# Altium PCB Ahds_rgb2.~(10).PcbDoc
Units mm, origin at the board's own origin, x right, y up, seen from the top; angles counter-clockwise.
Board outline 55.52 x 97.28 mm, 2 copper layers (Top Layer, Bottom Layer); 73 components, 40 nets, 226 pads, 37 vias.
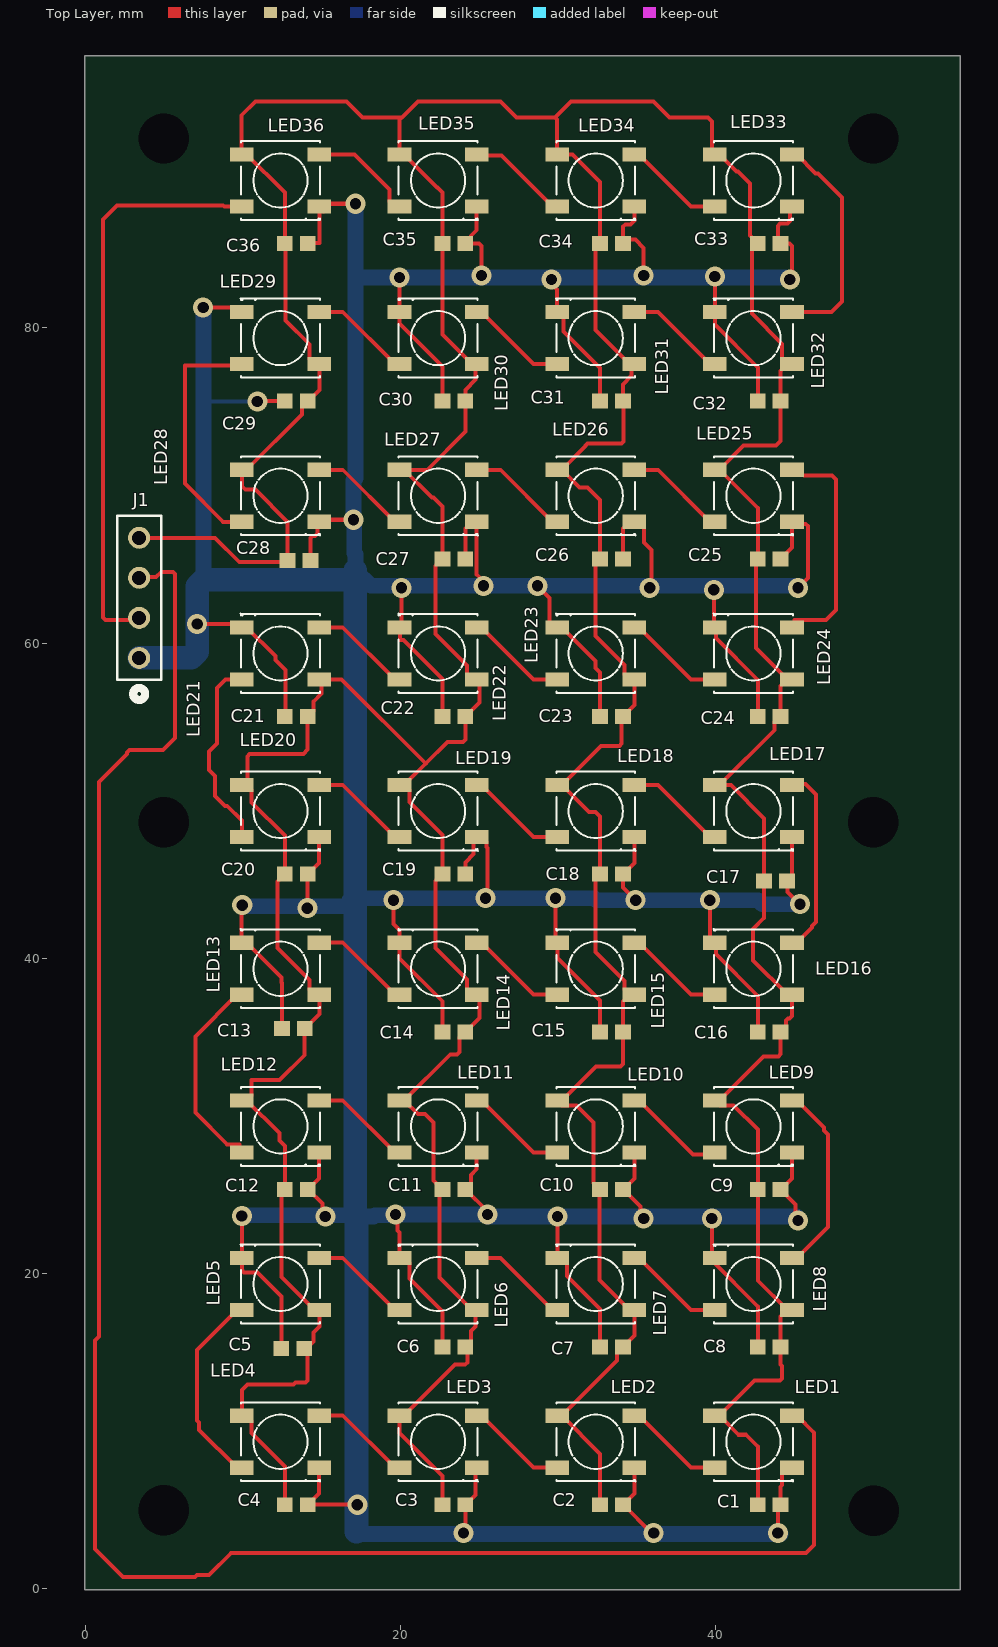
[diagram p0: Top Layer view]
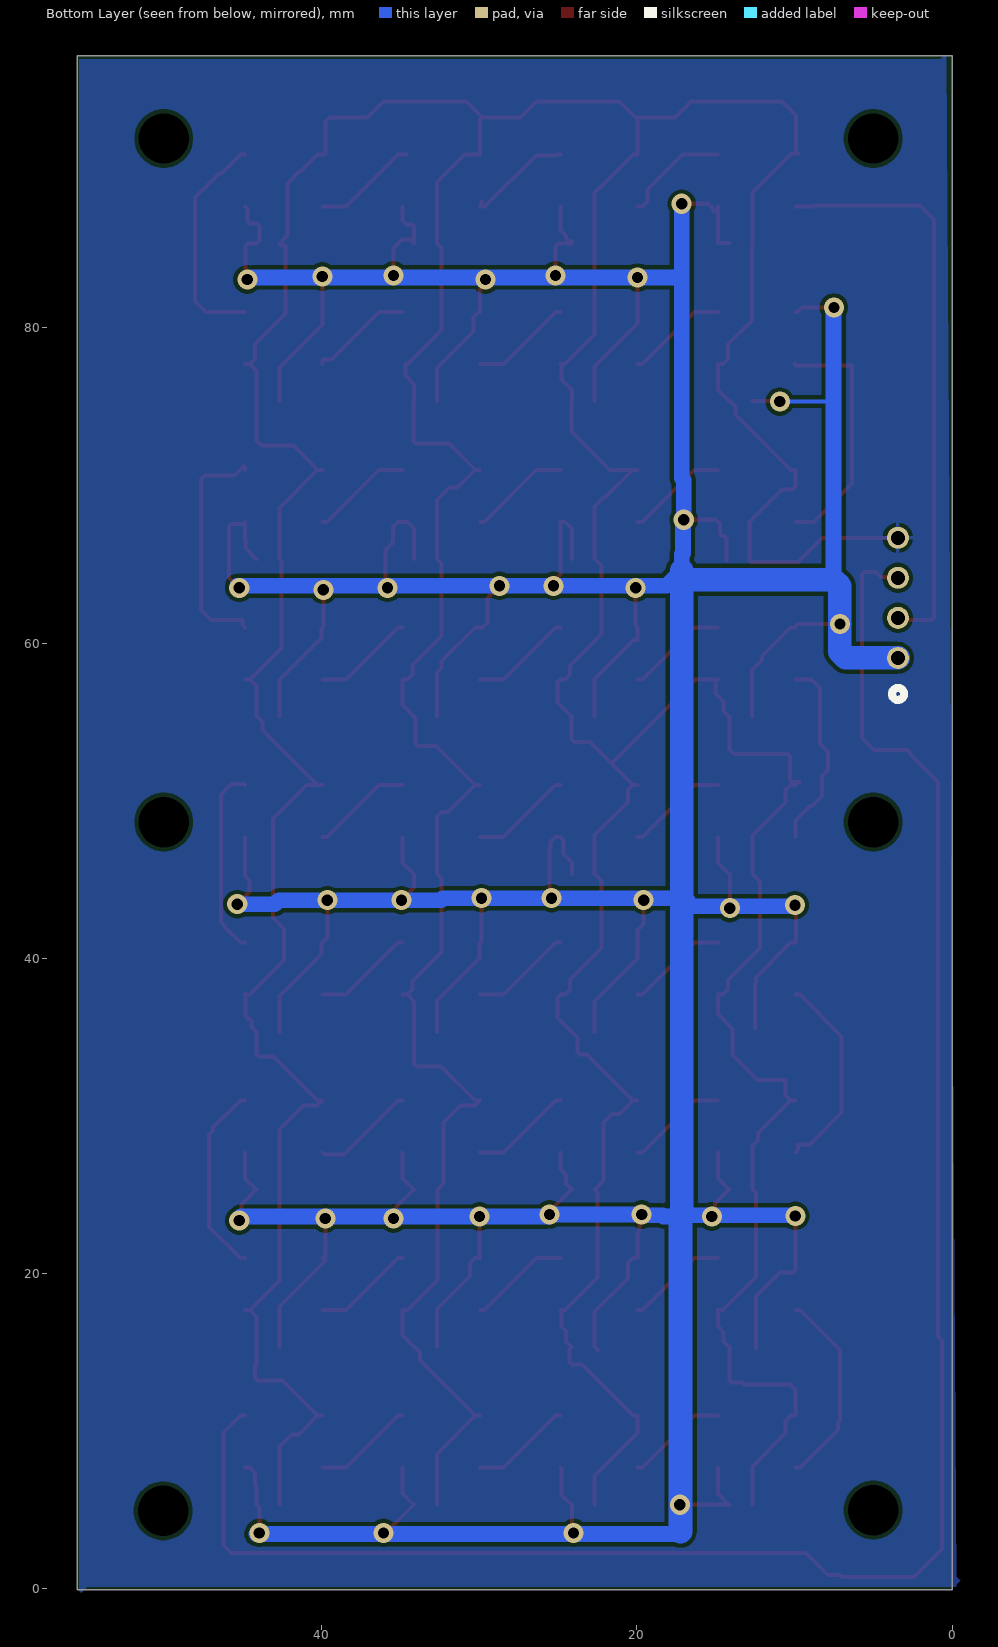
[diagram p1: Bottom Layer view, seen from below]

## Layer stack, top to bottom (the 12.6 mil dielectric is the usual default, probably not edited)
Top Solder: solder mask 0.0102, Solder Resist, Dk 3.5
Top Layer: signal copper 0.0356
Dielectric 1: dielectric 0.32, FR-4, Dk 4.8
Bottom Layer: signal copper 0.0356
Bottom Solder: solder mask 0.0102, Solder Resist, Dk 3.5

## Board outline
-0.018,-0.042 55.499,-0.042 55.499,97.24 -0.018,97.24

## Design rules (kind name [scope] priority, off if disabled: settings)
Clearance [All] p1: gap=0.254 ignorepadtopadclearanceinfootprint=TRUE
HoleSize [All] p1: absolutevalues=TRUE maxlimit=3.5 minlimit=0.025 maxpercent=80.000 minpercent=20.000
PolygonConnect [All] p1: connectstyle=Relief reliefconductorwidth=0.254 reliefentries=4 polygonreliefangle="90 Angle" airgapwidth=0.254
RoutingVias [All] p1: holewidth=0.711 width=1.27 viastyle="Through Hole" minholewidth=0.711 minwidth=1.27 maxholewidth=0.711 maxwidth=1.27
SolderMaskExpansion [All] p1: expansion=0.102 istentingtop=FALSE
Width [All] p1: maxlimit=2 minlimit=0.254 preferedwidth=0.254 minimp=50.000000 maximp=50.000000 favimp=50.000000
29 further rules are at their usual default settings.

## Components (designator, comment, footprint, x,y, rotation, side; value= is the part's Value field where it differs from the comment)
C1 "100nF" CAPC17595_87N_KEM#1 43.393,5.339 r180 top
C2 "100nF" CAPC17595_87N_KEM#1 33.393,5.339 r180 top
C3 "100nF" CAPC17595_87N_KEM#2 23.393,5.339 r180 top
C4 "100nF" CAPC17595_87N_KEM#3 13.393,5.339 r180 top
C5 "100nF" CAPC17595_87N_KEM#1 13.171,15.24 r0 top
C6 "100nF" CAPC17595_87N_KEM#1 23.393,15.339 r0 top
C7 "100nF" CAPC17595_87N_KEM#1 33.393,15.339 r0 top
C8 "100nF" CAPC17595_87N_KEM#1 43.393,15.339 r0 top
C9 "100nF" CAPC17595_87N_KEM#1 43.393,25.339 r180 top
C10 "100nF" CAPC17595_87N_KEM#1 33.393,25.339 r180 top
C11 "100nF" CAPC17595_87N_KEM#1 23.393,25.339 r180 top
C12 "100nF" CAPC17595_87N_KEM#1 13.393,25.339 r180 top
C13 "100nF" CAPC17595_87N_KEM#1 13.208,35.56 r0 top
C14 "100nF" CAPC17595_87N_KEM#1 23.393,35.339 r0 top
C15 "100nF" CAPC17595_87N_KEM#1 33.393,35.339 r0 top
C16 "100nF" CAPC17595_87N_KEM#1 43.393,35.339 r0 top
C17 "100nF" CAPC17595_87N_KEM#1 43.797,44.916 r180 top
C18 "100nF" CAPC17595_87N_KEM#1 33.393,45.339 r180 top
C19 "100nF" CAPC17595_87N_KEM#1 23.393,45.339 r180 top
C20 "100nF" CAPC17595_87N_KEM#1 13.393,45.339 r180 top
C21 "100nF" CAPC17595_87N_KEM#1 13.393,55.339 r0 top
C22 "100nF" CAPC17595_87N_KEM#1 23.393,55.339 r0 top
C23 "100nF" CAPC17595_87N_KEM#1 33.393,55.339 r0 top
C24 "100nF" CAPC17595_87N_KEM#1 43.393,55.339 r0 top
C25 "100nF" CAPC17595_87N_KEM#1 43.393,65.339 r180 top
C26 "100nF" CAPC17595_87N_KEM#1 33.393,65.339 r180 top
C27 "100nF" CAPC17595_87N_KEM#1 23.393,65.339 r180 top
C28 "100nF" CAPC17595_87N_KEM#1 13.571,65.236 r180 top
C29 "100nF" CAPC17595_87N_KEM#1 13.393,75.339 r0 top
C30 "100nF" CAPC17595_87N_KEM#1 23.393,75.339 r0 top
C31 "100nF" CAPC17595_87N_KEM#1 33.393,75.339 r0 top
C32 "100nF" CAPC17595_87N_KEM#1 43.393,75.339 r0 top
C33 "100nF" CAPC17595_87N_KEM#1 43.393,85.339 r180 top
C34 "100nF" CAPC17595_87N_KEM#1 33.393,85.339 r180 top
C35 "100nF" CAPC17595_87N_KEM#1 23.393,85.339 r180 top
C36 "100nF" CAPC17595_87N_KEM#1 13.393,85.339 r180 top
J1 "901471304" CONN04_901471304_MOL 3.429,59.055 r90 top
LED1 "WS2812B" *WS2812B_WS2812B(Primary) 42.393,9.339 r0 top
LED2 "WS2812B" *WS2812B_WS2812B(Primary) 32.393,9.339 r0 top
LED3 "WS2812B" *WS2812B_WS2812B(Primary) 22.393,9.339 r0 top
LED4 "WS2812B" *WS2812B_WS2812B(Primary) 12.393,9.339 r0 top
LED5 "WS2812B" *WS2812B_WS2812B(Primary) 12.393,19.339 r180 top
LED6 "WS2812B" *WS2812B_WS2812B(Primary) 22.393,19.339 r180 top
LED7 "WS2812B" *WS2812B_WS2812B(Primary) 32.393,19.339 r180 top
LED8 "WS2812B" *WS2812B_WS2812B(Primary) 42.393,19.339 r180 top
LED9 "WS2812B" *WS2812B_WS2812B(Primary) 42.393,29.339 r0 top
LED10 "WS2812B" *WS2812B_WS2812B(Primary) 32.393,29.339 r0 top
LED11 "WS2812B" *WS2812B_WS2812B(Primary) 22.393,29.339 r0 top
LED12 "WS2812B" *WS2812B_WS2812B(Primary) 12.393,29.339 r0 top
LED13 "WS2812B" *WS2812B_WS2812B(Primary) 12.393,39.339 r180 top
LED14 "WS2812B" *WS2812B_WS2812B(Primary) 22.393,39.339 r180 top
LED15 "WS2812B" *WS2812B_WS2812B(Primary) 32.393,39.339 r180 top
LED16 "WS2812B" *WS2812B_WS2812B(Primary) 42.393,39.339 r180 top
LED17 "WS2812B" *WS2812B_WS2812B(Primary) 42.393,49.339 r0 top
LED18 "WS2812B" *WS2812B_WS2812B(Primary) 32.393,49.339 r0 top
LED19 "WS2812B" *WS2812B_WS2812B(Primary) 22.393,49.339 r0 top
LED20 "WS2812B" *WS2812B_WS2812B(Primary) 12.393,49.339 r0 top
LED21 "WS2812B" *WS2812B_WS2812B(Primary) 12.393,59.339 r180 top
LED22 "WS2812B" *WS2812B_WS2812B(Primary) 22.393,59.339 r180 top
LED23 "WS2812B" *WS2812B_WS2812B(Primary) 32.393,59.339 r180 top
LED24 "WS2812B" *WS2812B_WS2812B(Primary) 42.393,59.339 r180 top
LED25 "WS2812B" *WS2812B_WS2812B(Primary) 42.393,69.339 r0 top
LED26 "WS2812B" *WS2812B_WS2812B(Primary) 32.393,69.339 r0 top
LED27 "WS2812B" *WS2812B_WS2812B(Primary) 22.393,69.339 r0 top
LED28 "WS2812B" *WS2812B_WS2812B(Primary) 12.393,69.339 r0 top
LED29 "WS2812B" *WS2812B_WS2812B(Primary) 12.393,79.339 r180 top
LED30 "WS2812B" *WS2812B_WS2812B(Primary) 22.393,79.339 r180 top
LED31 "WS2812B" *WS2812B_WS2812B(Primary) 32.393,79.339 r180 top
LED32 "WS2812B" *WS2812B_WS2812B(Primary) 42.393,79.339 r180 top
LED33 "WS2812B" *WS2812B_WS2812B(Primary) 42.393,89.339 r0 top
LED34 "WS2812B" *WS2812B_WS2812B(Primary) 32.393,89.339 r0 top
LED35 "WS2812B" *WS2812B_WS2812B(Primary) 22.393,89.339 r0 top
LED36 "WS2812B" *WS2812B_WS2812B(Primary) 12.393,89.339 r0 top

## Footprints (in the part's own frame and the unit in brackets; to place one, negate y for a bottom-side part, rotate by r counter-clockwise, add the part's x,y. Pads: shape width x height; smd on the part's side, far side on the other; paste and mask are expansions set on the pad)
*WS2812B_WS2812B(Primary) [mm]
  rect 1.5x0.9 smd: 1(2.45,-1.65) 2(2.45,1.65) 3(-2.45,1.65) 4(-2.45,-1.65)
  silkscreen extent -2.5,-2.52 2.52,2.5
CAPC17595_87N_KEM#1 [mm]
  rect 1x0.95 smd paste+0 mask+0: 1(-0.725,0) 2(0.725,0)
  body extent -0.87,-0.48 0.87,0.48, height 0.87
CAPC17595_87N_KEM#2 [mm]
  rect 1x0.95 smd paste+0.1 mask+0.1: 1(-0.725,0) 2(0.725,0)
  body extent -0.87,-0.48 0.87,0.48, height 0.87
CAPC17595_87N_KEM#3 [mm]
  rect 1x0.95 smd paste+0.102 mask+0: 1(-0.725,0)
  rect 1x0.95 smd paste+0 mask+0: 2(0.725,0)
  body extent -0.87,-0.48 0.87,0.48, height 0.87
CONN04_901471304_MOL [mil]
  round 55 hole 35 paste-99999 mask+0: 1(0,0) 2(100,0) 3(200,0) 4(300,0)
  silkscreen extent -105,-55 355,55

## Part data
C1 C2 C3 C4 C5 C6 C7 C8 C9 C10 C11 C12 C13 C14 C15 C16 C17 C18 C19 C20 C21 C22 C23 C24 C25 C26 C27 C28 C29 C30 C31 C32 C33 C34 C35 C36: library part C0603C103K4RECTU, "ESD SMD Comm X7R, Ceramic, 0.01 uF, 10%, 16 VDC, X7R, SMD, MLCC, Temperature Stable, Electro Static Discharge, Class II, 0603", Manufacturer_Name=Kemet
J1: "C-Grid III PCB Receptacle, 2.54mm Pitch, Single Row, Vertical, Shrouded, 4 Circuits, 0.76Âµm Gold (Au) Plating", Manufacturer_Name=Molex
LED1 LED2 LED3 LED4 LED5 LED6 LED7 LED8 LED9 LED10 LED11 LED12 LED13 LED14 LED15 LED16 LED17 LED18 LED19 LED20 LED21 LED22 LED23 LED24 LED25 LED26 LED27 LED28 LED29 LED30 LED31 LED32 LED33 LED34 LED35 LED36: "Intelligent control LED integrated light source", Package=None

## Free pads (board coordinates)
  round 1.524 hole 3.2: 1(5,5) 2(50.038,4.953) 3(50,48.64) 4(50,92) 5(5,92) 6(5,48.64)

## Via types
v1: diameter 1.27, hole 0.711, Top Layer to Bottom Layer, 37 vias

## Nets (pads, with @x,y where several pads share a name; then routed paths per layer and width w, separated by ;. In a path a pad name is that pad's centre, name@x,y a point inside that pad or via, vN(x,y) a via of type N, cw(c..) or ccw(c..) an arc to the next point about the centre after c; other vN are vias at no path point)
5V: C1.1 C2.1 C3.1 C4.1 C5.1 C6.1 C7.1 C8.1 C9.1 C10.1 C11.1 C12.1 C13.1 C14.1 C15.1 C16.1 C17.1 C18.1 C19.1 C20.1 C21.1 C22.1 C23.1 C24.1 C25.1 C26.1 C27.1 C28.1 C29.1 C30.1 C31.1 C32.1 C33.1 C34.1 C35.1 C36.1 J1.1 LED1.1 LED2.1 LED3.1 LED4.1 LED5.1 LED6.1 LED7.1 LED8.1 LED9.1 LED10.1 LED11.1 LED12.1 LED13.1 LED14.1 LED15.1 LED16.1 LED17.1 LED18.1 LED19.1 LED20.1 LED21.1 LED22.1 LED23.1 LED24.1 LED25.1 LED26.1 LED27.1 LED28.1 LED29.1 LED30.1 LED31.1 LED32.1 LED33.1 LED34.1 LED35.1 LED36.1 | length 540.2
  Top Layer w0.254: J1.1 3.556,59.055 J1.1@3.683,59.182 ; v1(7.112,61.214) 9.779,61.214 LED21.1@9.973,61.02 ; v1(7.493,81.28) 9.525,81.28 9.816,80.989 LED29.1 ; v1(9.943,23.659) LED5.1 9.943,20.215 10.092,20.066 10.922,20.066 12.446,18.542 C5.1 ; LED21.1 10.243,60.989 12.065,59.167 12.065,58.928 12.7,58.293 12.7,55.372 C21.1 ; v1@10.033,43.434 9.906,43.307 9.906,41.275 9.943,41.238 LED13.1 10.243,40.989 12.446,38.786 12.446,38.481 12.483,38.444 C13.1 ; v1(10.922,75.311) 10.95,75.339 C29.1 ; v1(14.097,43.18) 14.097,45.318 C20.1 14.143,45.339 14.843,46.039 LED20.1 ; C4.1 C4.1@14.143,5.339 ; C12.1 C12.1@14.143,25.339 ; C36.1 14.145,85.366 14.859,85.366 LED36.1@14.859,87.63 ; C28.1 14.296,66.653 14.445,66.802 14.583,66.802 14.732,66.951 14.732,67.578 14.972,67.818 v1(17.018,67.818) ; LED4.1 14.843,6.039 C4.1@14.143,5.339 ; LED12.1 14.843,26.039 C12.1@14.143,25.339 ; LED36.1 14.843,87.646 LED36.1@14.859,87.63 ; v1(15.24,23.622) 15.046,23.816 15.046,24.437 C12.1@14.143,25.339 ; v1(17.145,87.862) 15.466,87.862 15.123,87.519 15.123,87.366 LED36.1@14.859,87.63 ; v1@17.272,5.334 v1(17.267,5.339) C4.1@14.143,5.339 ; v1(19.558,43.688) 19.558,42.164 19.685,42.037 19.693,42.037 19.943,41.787 LED14.1 19.943,40.001 22.668,37.276 C14.1 ; v1(19.685,23.749) 19.816,23.618 19.816,22.733 19.943,22.606 LED6.1 20.243,20.989 20.566,20.666 20.566,19.69 22.668,17.588 C6.1 22.643,15.339 22.479,15.175 C6.1@22.479,15.113 ; v1@19.812,83.312 v1(19.943,83.181) LED30.1 19.943,80.26 22.668,77.535 C30.1 ; v1(20.066,63.5) 20.066,61.112 LED22.1 19.961,60.972 19.961,60.198 20.193,60.198 22.668,57.723 C22.1 ; v1(24.003,3.556) 24.118,3.671 C3.1 24.143,5.339 24.765,5.961 24.765,7.62 24.834,7.689 LED3.1 ; C11.1 C11.1@24.143,25.339 ; C19.1 24.118,46.089 24.638,46.609 24.638,47.484 LED19.1 25.143,47.689 25.466,47.366 25.466,47.051 25.527,46.99 25.527,43.942 v1(25.4,43.815) ; C27.1 24.118,67.264 24.543,67.689 LED27.1 24.843,64.332 25.273,63.902 v1(25.273,63.627) ; LED11.1 24.843,26.621 24.491,26.269 24.491,25.687 C11.1@24.143,25.339 ; LED35.1 24.843,86.184 24.491,85.832 24.491,85.687 24.275,85.471 24.13,85.471 24.118,85.459 C35.1 24.997,85.339 25.146,85.19 v1(25.146,83.312) ; v1(25.527,23.749) 25.527,23.955 C11.1@24.143,25.339 ; v1(28.702,63.627) 29.464,62.865 29.464,61.312 29.787,60.989 LED23.1 30.243,60.989 32.385,58.847 32.385,58.42 32.668,58.137 C23.1 ; v1(29.591,83.058) 29.591,82.783 29.943,82.431 LED31.1 30.03,80.989 30.353,80.666 30.353,79.756 32.668,77.441 C31.1 ; v1(29.845,43.815) 29.845,41.087 LED15.1 29.972,40.96 29.972,40.005 32.668,37.309 C15.1 ; v1(29.972,23.622) 29.972,21.018 LED7.1 30.243,20.989 30.566,20.666 30.566,19.853 32.668,17.751 C7.1 ; C2.1 C2.1@34.143,5.339 ; C10.1 C10.1@34.143,25.339 ; C26.1 34.118,67.264 34.543,67.689 LED26.1 35.143,67.689 35.466,67.366 35.466,66.388 35.941,65.913 35.941,63.627 v1(35.814,63.5) ; LED2.1 34.843,6.039 C2.1@34.143,5.339 ; LED10.1 34.843,26.039 C10.1@34.143,25.339 ; LED18.1 34.843,46.039 34.143,45.339 C18.1 34.118,44.495 v1(34.925,43.688) ; LED34.1 34.843,86.792 34.604,86.554 34.267,86.554 34.118,86.405 C34.1 34.377,85.598 34.903,85.598 35.433,85.068 v1(35.433,83.312) ; v1(35.433,23.495) 35.239,23.689 35.239,24.244 C10.1@34.143,25.339 ; v1(36.068,3.556) 35.926,3.556 C2.1@34.143,5.339 ; v1(39.624,43.688) 39.624,41.308 LED16.1 40.005,40.927 40.005,40.259 42.668,37.596 C16.1 ; v1(39.751,23.495) LED8.1@39.751,21.181 ; v1(39.878,63.373) 39.878,61.054 LED24.1 40.005,60.927 40.005,60.325 42.668,57.662 C24.1 ; v1@39.878,83.312 v1(39.943,83.247) LED32.1 39.943,80.199 42.668,77.474 C32.1 ; LED8.1 LED8.1@39.751,21.181 ; C8.1 42.668,17.911 39.751,20.828 LED8.1@39.751,21.181 ; v1(43.942,3.556) 43.942,5.163 C1.1 44.118,6.476 44.22,6.578 44.22,7.366 44.543,7.689 LED1.1 ; C9.1 C9.1@44.143,25.339 ; C25.1 44.143,65.339 44.491,65.687 44.491,65.712 44.831,66.052 44.831,66.548 44.843,66.56 LED25.1 44.968,67.564 45.698,67.564 45.847,67.415 45.847,64.135 v1(45.212,63.5) ; v1(44.704,83.058) 44.831,83.185 44.831,85.195 44.682,85.344 44.123,85.344 C33.1 43.942,85.515 43.942,86.465 44.091,86.614 44.555,86.614 44.704,86.763 44.704,87.55 LED33.1 ; LED9.1 44.843,26.039 C9.1@44.143,25.339 ; LED17.1 44.843,45.237 C17.1 44.564,44.874 44.564,44.209 v1(45.339,43.434) ; v1(45.212,23.368) 45.073,23.507 45.073,24.384 44.491,24.966 44.491,24.991 C9.1@44.143,25.339
  Bottom Layer w0.254: J1.1@3.302,59.309 3.429,59.182 J1.1 ; v1(7.493,81.28) v1@7.515,81.258 ; 7.515,75.311 10.541,75.311 10.922,74.93 v1(10.922,75.311) ; v1@9.906,23.876 v1@10.086,23.696 ; v1@10.16,43.307 v1@10.287,43.18 ; 16.51,64.008 16.532,63.986 ; 16.764,43.329 16.764,43.688 ; 17.145,23.771 17.219,23.696 17.294,23.622 ; 17.145,44.069 17.399,43.815 ; 17.219,3.63 17.368,3.482 ; v1@44.122,3.482 v1@44.196,3.556 ; v1@44.45,83.185 44.577,83.312 v1@44.704,83.312 ; v1@45.121,23.622 v1@45.189,23.69
  Bottom Layer w1: 7.515,64.008 7.515,75.311 v1@7.515,81.258 ; v1@10.086,23.696 17.219,23.696 ; v1@10.16,43.307 16.742,43.307 ; 16.532,63.986 17.145,64.599 ; 16.764,43.688 17.145,44.069 ; v1(17.145,87.862) 17.145,83.185 ; 17.294,23.622 18.294,23.622 18.369,23.697 19.633,23.697 v1(19.685,23.749) 25.402,23.749 v1@25.527,23.624 ; 17.368,3.482 v1@44.122,3.482 ; 17.399,43.815 v1(25.4,43.815) v1(29.845,43.815) 32.29,43.815 32.417,43.688 v1(34.925,43.688) v1(39.624,43.688) 42.704,43.688 42.958,43.434 v1(45.339,43.434) ; v1@25.527,23.622 v1(29.972,23.622) v1@45.121,23.622 ; v1@44.45,83.185 17.145,83.185 ; v1@45.339,63.627 v1(28.702,63.627) v1(25.273,63.627) 18.117,63.627 17.145,64.599 ; 17.145,64.599 17.145,65.618 17.07,65.693 17.07,67.766 v1(17.018,67.818) 17.018,70.326 17.145,70.453 17.145,83.185
  Bottom Layer w1.5: J1.1 6.731,59.055 7.112,59.436 7.112,63.605 7.515,64.008 16.51,64.008 ; 17.145,23.771 17.145,44.069 17.145,64.599 ; 17.219,3.63 17.219,23.696
  other v1: 9.97,43.37
GND: C1.2 C2.2 C3.2 C4.2 C5.2 C6.2 C7.2 C8.2 C9.2 C10.2 C11.2 C12.2 C13.2 C14.2 C15.2 C16.2 C17.2 C18.2 C19.2 C20.2 C21.2 C22.2 C23.2 C24.2 C25.2 C26.2 C27.2 C28.2 C29.2 C30.2 C31.2 C32.2 C33.2 C34.2 C35.2 C36.2 J1.4 LED1.3 LED2.3 LED3.3 LED4.3 LED5.3 LED6.3 LED7.3 LED8.3 LED9.3 LED10.3 LED11.3 LED12.3 LED13.3 LED14.3 LED15.3 LED16.3 LED17.3 LED18.3 LED19.3 LED20.3 LED21.3 LED22.3 LED23.3 LED24.3 LED25.3 LED26.3 LED27.3 LED28.3 LED29.3 LED30.3 LED31.3 LED32.3 LED33.3 LED34.3 LED35.3 LED36.3 | length 490.1
  Top Layer w0.254: J1.4 8.255,66.675 9.779,65.151 12.761,65.151 C28.2 12.846,67.672 10.795,69.723 10.16,69.723 9.943,69.94 LED28.3 10.243,70.989 13.745,74.491 13.745,74.991 14.093,75.339 C29.2 14.143,75.339 14.859,76.055 14.859,77.689 LED29.3 14.543,77.689 14.22,78.012 14.22,78.95 12.7,80.47 12.7,85.217 12.668,85.249 C36.2 12.668,88.564 10.173,91.059 9.779,91.059 9.906,91.186 9.906,93.472 10.795,94.361 16.567,94.361 17.583,93.345 20.092,93.345 ; LED20.3@9.652,51.181 LED20.3@9.751,51.181 ; LED12.3 LED12.3@10.243,30.989 ; C4.2 12.668,7.779 10.566,9.881 10.566,10.666 10.243,10.989 LED4.3 9.943,12.61 10.287,12.954 13.208,12.954 13.335,13.081 13.969,13.081 14.118,13.23 14.118,15.339 14.143,15.339 14.491,15.687 14.491,16.269 14.859,16.637 14.859,17.673 LED5.3 14.543,17.689 12.446,19.786 12.446,25.117 C12.2 12.668,28.099 12.319,28.448 12.319,28.913 LED12.3@10.243,30.989 ; LED11.3 LED11.3@20.243,30.989 ; LED19.3 LED19.3@20.243,50.989 ; LED27.3 LED27.3@20.243,70.989 ; C3.2 22.668,7.174 19.943,9.899 LED3.3 20.243,10.989 23.478,14.224 24.108,14.224 24.257,14.373 24.257,15.2 C6.2 24.143,15.339 24.491,15.687 24.491,16.363 24.765,16.637 24.765,17.611 LED6.3 24.543,17.689 22.479,19.753 22.479,25.15 C11.2 22.643,25.339 22.295,25.687 22.295,25.712 22.098,25.909 22.098,29.591 21.56,30.129 21.104,30.129 LED11.3@20.243,30.989 ; LED2.3 LED2.3@30.243,10.989 ; LED18.3 LED18.3@30.243,50.989 ; LED26.3 LED26.3@30.243,70.989 ; C10.2@32.639,25.31 32.639,19.593 34.543,17.689 LED7.3 34.843,16.064 34.491,15.712 34.491,15.687 34.143,15.339 C7.2 34.093,15.339 33.745,14.991 33.745,14.491 LED2.3@30.243,10.989 ; C10.2@32.643,25.339 32.295,25.687 32.295,25.712 32.258,25.749 32.258,29.591 31.183,30.666 30.266,30.666 LED10.3 30.243,30.989 32.401,33.147 33.969,33.147 34.118,33.296 C15.2 34.118,37.264 LED15.3@34.543,37.689 ; C2.2 32.668,8.564 LED2.3@30.243,10.989 ; LED15.3 LED15.3@34.543,37.689 ; LED1.3 LED1.3@40.243,10.989 ; LED17.3 LED17.3@40.243,50.989 ; LED25.3 LED25.3@40.243,70.989 ; C1.2 42.668,9.021 41.91,9.779 41.453,9.779 LED1.3@40.243,10.989 ; LED8.3 LED8.3@44.543,17.689 ; LED24.3 LED24.3@44.543,57.689 ; LED32.3 LED32.3@44.543,77.689 ; LED20.3@9.751,51.181 10.156,51.181 10.287,51.312 10.287,52.81 10.436,52.959 13.843,52.959 14.118,53.234 C21.2 14.143,55.339 14.491,55.687 14.491,56.274 15.008,56.791 15.008,57.525 LED21.3 16.275,57.689 21.609,52.355 ; LED20.3@9.751,51.181 LED20.3 10.243,50.989 10.566,50.666 10.566,49.886 12.668,47.784 C20.2 12.643,45.339 12.295,44.991 12.295,44.966 12.192,44.863 12.192,40.64 14.22,38.612 14.22,38.012 14.543,37.689 LED13.3 14.859,37.673 14.859,36.461 13.958,35.56 C13.2 13.933,33.872 12.344,32.283 10.566,32.283 10.566,31.312 LED12.3@10.243,30.989 ; 20.092,93.345 21.108,94.361 26.353,94.361 27.369,93.345 29.794,93.345 ; 20.092,93.345 19.943,93.196 LED35.3 20.243,90.989 22.332,88.9 22.352,88.9 22.668,88.584 C35.2 22.668,79.564 24.543,77.689 LED30.3 24.765,77.611 24.765,76.708 24.118,76.061 C30.2 24.13,75.327 24.13,73.406 21.713,70.989 LED27.3@20.243,70.989 ; LED11.3@20.243,30.989 23.163,33.909 23.6,33.909 23.749,34.058 23.749,34.991 24.097,35.339 C14.2 24.143,35.339 25.019,36.215 25.019,37.513 LED14.3 24.543,37.689 24.22,38.012 24.22,38.645 22.225,40.64 22.225,44.896 22.295,44.966 22.295,44.991 22.643,45.339 C19.2 22.668,47.814 20.566,49.916 20.566,50.666 LED19.3@20.243,50.989 ; LED19.3@20.243,50.989 21.609,52.355 ; LED27.3@20.243,70.989 22.017,69.215 22.098,69.215 22.668,68.645 C27.2 22.643,65.339 22.295,64.991 22.295,64.966 22.225,64.896 22.225,60.579 24.22,58.584 24.22,58.012 24.543,57.689 LED22.3 25.019,57.513 25.019,56.215 24.143,55.339 C22.2 24.13,55.327 24.13,53.87 23.981,53.721 22.975,53.721 21.609,52.355 ; 29.794,93.345 30.81,94.361 36.055,94.361 37.071,93.345 39.497,93.345 39.751,93.091 39.751,91.059 39.821,90.989 LED33.3 40.243,90.989 41.322,89.91 41.408,89.91 42.164,89.154 42.164,85.843 42.295,85.712 42.295,85.687 42.643,85.339 C33.2 42.537,85.208 42.291,85.208 42.291,80.899 44.22,78.97 44.22,78.012 LED32.3@44.543,77.689 ; 29.794,93.345 29.943,93.196 LED34.3 30.931,90.989 32.668,89.252 C34.2 32.385,85.056 32.385,79.847 34.543,77.689 34.693,77.689 34.671,77.667 34.671,76.962 34.118,76.409 C31.2 34.163,75.294 34.163,72.793 34.014,72.644 31.877,72.644 31.75,72.517 31.75,72.496 LED26.3@30.243,70.989 ; LED18.3@30.243,50.989 32.721,53.467 33.887,53.467 34.036,53.616 34.036,55.257 C23.2 34.143,55.339 34.491,55.687 34.491,55.712 34.843,56.064 LED23.3 34.543,57.689 34.22,58.012 34.22,58.617 32.385,60.452 32.385,65.056 C26.2 32.668,69.066 31.868,69.866 31.366,69.866 LED26.3@30.243,70.989 ; LED18.3@30.243,50.989 31.956,49.276 32.385,49.276 32.668,48.993 C18.2 32.385,45.056 32.385,40.386 34.22,38.551 34.22,38.012 LED15.3@34.543,37.689 ; LED1.3@40.243,10.989 42.462,13.208 44.069,13.208 44.218,13.357 44.218,14.124 44.118,14.224 C8.2 44.118,17.264 LED8.3@44.543,17.689 ; LED17.3@40.243,50.989 40.959,50.989 43.072,48.876 C17.2 43.072,42.572 42.364,41.864 42.364,39.868 44.543,37.689 LED16.3 44.831,37.677 44.831,36.344 44.682,36.195 44.599,36.195 44.45,36.046 44.45,35.671 C16.2 44.118,33.931 43.969,33.782 43.036,33.782 40.243,30.989 LED9.3 40.266,30.666 41.136,30.666 42.672,29.13 42.672,25.343 C9.2 42.668,19.564 LED8.3@44.543,17.689 ; LED17.3@40.243,50.989 43.745,54.491 43.745,54.991 44.093,55.339 C24.2 44.118,57.264 LED24.3@44.543,57.689 ; LED25.3@40.243,70.989 41.771,72.517 43.815,72.517 44.118,72.82 C32.2 44.118,77.264 LED32.3@44.543,77.689 ; LED25.3@40.243,70.989 42.668,68.564 C25.2 42.545,65.216 42.545,59.687 LED24.3@44.543,57.689
NetC5_1: 
NetJ1_2: J1.2 LED36.4 | length 36.8
  Top Layer w0.254: J1.2 3.302,61.468 1.292,61.468 1.143,61.617 1.143,86.868 2.032,87.757 8.763,87.757 8.831,87.689 LED36.4
NetJ1_3: J1.3 LED1.2 | length 123.8
  Top Layer w0.254: J1.3 3.476,64.182 4.508,64.182 4.843,64.516 5.566,64.516 5.715,64.367 5.715,53.975 4.953,53.213 2.816,53.213 2.667,53.064 2.667,52.959 0.889,51.181 0.889,16.024 0.635,15.77 0.635,2.54 2.413,0.762 6.985,0.762 7.112,0.889 7.874,0.889 9.271,2.286 45.72,2.286 46.226,2.792 46.226,9.906 45.143,10.989 LED1.2
NetLED1_4: LED1.4 LED2.2 | length 6.5
  Top Layer w0.254: LED2.2 35.143,10.989 38.443,7.689 LED1.4
NetLED2_4: LED2.4 LED3.2 | length 6.5
  Top Layer w0.254: LED3.2 25.143,10.989 28.443,7.689 LED2.4
NetLED3_4: LED3.4 LED4.2 | length 6.5
  Top Layer w0.254: LED4.2 16.343,10.989 19.643,7.689 LED3.4
NetLED4_4: LED4.4 LED5.2 | length 12.7
  Top Layer w0.254: LED4.4 9.643,7.689 7.239,10.093 7.239,10.541 7.112,10.668 7.112,15.158 9.643,17.689 LED5.2
NetLED5_4: LED5.4 LED6.2 | length 6.5
  Top Layer w0.254: LED5.4 16.343,20.989 19.643,17.689 LED6.2
NetLED6_4: LED6.4 LED7.2 | length 6.5
  Top Layer w0.254: LED6.4 26.343,20.989 29.643,17.689 LED7.2
NetLED7_4: LED7.4 LED8.2 | length 6.5
  Top Layer w0.254: LED7.4 35.143,20.989 38.443,17.689 LED8.2
NetLED8_4: LED8.4 LED9.2 | length 12.2
  Top Layer w0.254: LED8.4 45.143,20.989 47.117,22.963 47.117,28.829 46.863,29.083 46.863,29.269 45.143,30.989 LED9.2
NetLED9_4: LED9.4 LED10.2 | length 6.6
  Top Layer w0.254: LED10.2 35.143,30.989 38.573,27.559 39.813,27.559 LED9.4
NetLED10_4: LED10.4 LED11.2 | length 6.5
  Top Layer w0.254: LED11.2 25.143,30.989 28.443,27.689 LED10.4
NetLED11_4: LED11.4 LED12.2 | length 6.5
  Top Layer w0.254: LED12.2 16.343,30.989 19.643,27.689 LED11.4
NetLED12_4: LED12.4 LED13.2 | length 13.1
  Top Layer w0.254: LED12.4 9.779,27.853 9.779,28.194 9.017,28.194 7.006,30.205 7.006,35.052 9.643,37.689 LED13.2
NetLED13_4: LED13.4 LED14.2 | length 6.5
  Top Layer w0.254: LED13.4 16.343,40.989 19.643,37.689 LED14.2
NetLED14_4: LED14.4 LED15.2 | length 6.5
  Top Layer w0.254: LED14.4 25.143,40.989 28.443,37.689 LED15.2
NetLED15_4: LED15.4 LED16.2 | length 6.5
  Top Layer w0.254: LED15.4 35.143,40.989 38.443,37.689 LED16.2
NetLED16_4: LED16.4 LED17.2 | length 12
  Top Layer w0.254: LED16.4 45.143,40.989 46.101,41.947 46.101,42.037 46.355,42.291 46.355,50.397 45.698,51.054 44.908,51.054 LED17.2
NetLED17_4: LED17.4 LED18.2 | length 6.5
  Top Layer w0.254: LED18.2 36.343,50.989 39.643,47.689 LED17.4
NetLED18_4: LED18.4 LED19.2 | length 6.5
  Top Layer w0.254: LED19.2 25.143,50.989 28.443,47.689 LED18.4
NetLED19_4: LED19.4 LED20.2 | length 6.5
  Top Layer w0.254: LED20.2 16.343,50.989 19.643,47.689 LED19.4
NetLED20_4: LED20.4 LED21.2 | length 12.4
  Top Layer w0.254: LED20.4 9.943,48.731 9.017,49.657 8.89,49.657 8.255,50.292 8.255,51.562 7.874,51.943 7.874,53.118 8.382,53.626 8.382,57.15 8.921,57.689 LED21.2
NetLED21_4: LED21.4 LED22.2 | length 6.5
  Top Layer w0.254: LED21.4 16.343,60.989 19.643,57.689 LED22.2
NetLED22_4: LED22.4 LED23.2 | length 6.5
  Top Layer w0.254: LED22.4 25.143,60.989 28.443,57.689 LED23.2
NetLED23_4: LED23.4 LED24.2 | length 6.5
  Top Layer w0.254: LED23.4 35.143,60.989 38.443,57.689 LED24.2
NetLED24_4: LED24.4 LED25.2 | length 15.1
  Top Layer w0.254: LED24.4 44.992,61.138 44.992,61.468 46.99,61.468 47.625,62.103 47.625,70.358 47.371,70.612 45.593,70.612 45.539,70.666 45.466,70.666 44.958,71.174 44.958,71.247 44.843,71.132 LED25.2
NetLED25_4: LED25.4 LED26.2 | length 6.5
  Top Layer w0.254: LED26.2 36.343,70.989 39.643,67.689 LED25.4
NetLED26_4: LED26.4 LED27.2 | length 6.5
  Top Layer w0.254: LED27.2 26.343,70.989 29.643,67.689 LED26.4
NetLED27_4: LED27.4 LED28.2 | length 6.5
  Top Layer w0.254: LED28.2 16.343,70.989 19.643,67.689 LED27.4
NetLED28_4: LED28.4 LED29.2 | length 15.8
  Top Layer w0.254: LED28.4 9.941,67.691 8.763,67.691 6.35,70.104 6.35,77.597 9.906,77.597 9.998,77.689 LED29.2
NetLED29_4: LED29.4 LED30.2 | length 6.5
  Top Layer w0.254: LED29.4 16.343,80.989 19.643,77.689 LED30.2
NetLED30_4: LED30.4 LED31.2 | length 6.5
  Top Layer w0.254: LED30.4 25.143,80.989 28.443,77.689 LED31.2
NetLED31_4: LED31.4 LED32.2 | length 6.6
  Top Layer w0.254: LED31.4 36.343,80.989 39.354,77.978 39.878,77.978 39.943,77.913 LED32.2
NetLED32_4: LED32.4 LED33.2 | length 14.3
  Top Layer w0.254: LED32.4 47.334,80.989 48.006,81.661 48.006,88.265 46.482,89.789 46.343,89.789 45.143,90.989 LED33.2
NetLED33_4: LED33.4 LED34.2 | length 6.7
  Top Layer w0.254: LED34.2@34.614,90.989 LED34.2 35.143,90.989 38.443,87.689 LED33.4
NetLED34_4: LED34.4 LED35.2 | length 6.8
  Top Layer w0.254: LED35.2 25.089,90.989 25.146,90.932 26.4,90.932 29.643,87.689 LED34.4 29.845,87.787 LED34.4@29.845,88.011
NetLED35_4: LED35.4 LED36.2 | length 6.9
  Top Layer w0.254: LED36.2 17.088,90.989 19.32,88.757 19.32,88.012 19.643,87.689 LED35.4

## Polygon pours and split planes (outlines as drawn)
GND on Bottom Layer "GND_BOT" (solid, remove dead copper, pour order 2): 0.381,96.266 54.483,96.266 54.61,96.393 54.61,0.254 -0.254,0.254 -0.508,0.508 0.254,1.27 0.254,1.397
GND on Bottom Layer "GND_TOP" (solid, remove dead copper, pour order 0): 0.381,97.409 0.762,97.028 55.372,97.028 55.372,-0.127 55.245,-0.254 54.864,0.127 -0.254,0.127 -0.254,0.381

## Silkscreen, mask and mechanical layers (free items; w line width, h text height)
Mechanical 1:
  circle w0.254: c50,92 r3.5
  circle w0.254: c5,92 r3.5
  circle w0.254: c5,48.64 r3.5
  circle w0.254: c50,48.64 r3.5
  circle w0.254: c50,5 r3.5
  circle w0.254: c5,5 r3.5

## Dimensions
-0.018,-0.042 to -0.018,97.24 on Mechanical 1
-0.018,97.24 to 55.499,97.24 on Mechanical 1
